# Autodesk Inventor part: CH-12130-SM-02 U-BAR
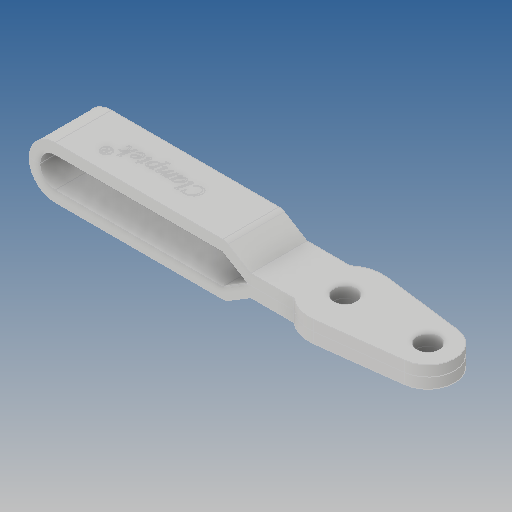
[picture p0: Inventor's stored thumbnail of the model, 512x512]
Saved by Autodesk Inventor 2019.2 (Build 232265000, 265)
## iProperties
Created: 2012-09
Part Number: CH-12130-SM-02 U-BAR
Material: Ogólny
Document SubType Name: Modeling
Designer: CADENGINEERING4
Density: 1 g/cm^3
Appearance: Domyślna
Author: CADENGINEERING4
Revision Number: ÈÎºÎ
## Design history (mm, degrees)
feature "ÇÐ³ý-À­Éì2"
feature "ÇÐ³ý-À­Éì6"
node "Bryła1"
node "Bryła2"
